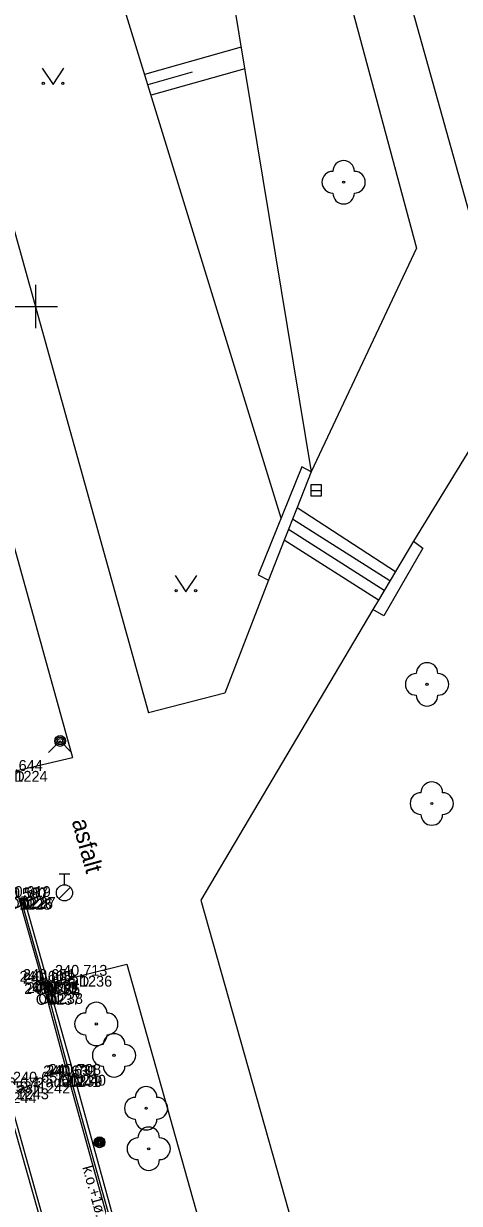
# Model space of a CAD drawing. Extents: x -599098 to -598820, y -1159597 to -1158744.
# Drawn here: x -598950.6 to -598930.4, y -1159141.4 to -1159086.9 of the extents above; entities that cross this region are included whole.
import ezdxf

# ---------------------------------------------------------------- set-up
doc = ezdxf.new("R2010")
doc.units = 0
for name, color, linetype in [('body', 7, 'Continuous'), ('druh pozemku stromy', 7, 'Continuous'), ('hektometrická síť', 7, 'Continuous'), ('kresba', 7, 'Continuous'), ('kódy bodů', 7, 'Continuous'), ('popisy', 7, 'Continuous'), ('vodorovné dopravní značení_bílé', 7, 'Continuous'), ('výšky bodů', 7, 'Continuous'), ('značky IS', 7, 'Continuous'), ('čísla bodů', 7, 'Continuous')]:
    doc.layers.add(name, color=color, linetype=linetype)

msp = doc.modelspace()

# ---------------------------------------------------------------- linework, layer by layer
at = {"layer": 'body'}
for p, q in [((-598949.602, -1159131.15), (-598949.602, -1159131.15)), ((-598949.491, -1159131.071), (-598949.491, -1159131.071)), ((-598949.444, -1159131.241), (-598949.444, -1159131.241)), ((-598947.965, -1159130.878), (-598947.965, -1159130.878)), ((-598949.433, -1159131.716), (-598949.433, -1159131.716)), ((-598949.315, -1159131.673), (-598949.315, -1159131.673)), ((-598948.51, -1159135.517), (-598948.51, -1159135.517)), ((-598948.421, -1159135.492), (-598948.421, -1159135.492)), ((-598948.253, -1159135.448), (-598948.253, -1159135.448)), ((-598949.904, -1159135.807), (-598949.904, -1159135.807))]:
    msp.add_line(p, q, dxfattribs=at)
at = {"layer": 'druh pozemku stromy'}
for points in [[(-598949.706, -1159088.996), (-598949.206, -1159089.746), (-598948.706, -1159088.996)], [(-598943.574, -1159112.407), (-598943.074, -1159113.157), (-598942.574, -1159112.407)]]:
    msp.add_lwpolyline(points, dxfattribs=at)
for centre in [(-598949.656, -1159089.695), (-598948.757, -1159089.695), (-598935.79, -1159094.26), (-598943.524, -1159113.107), (-598942.624, -1159113.107), (-598931.94, -1159117.43), (-598931.72, -1159122.93), (-598947.21, -1159133.1), (-598946.39, -1159134.55), (-598944.91, -1159136.99), (-598944.79, -1159138.86)]:
    msp.add_circle(centre, 0.05, dxfattribs=at)
for centre, start, end in [((-598935.79, -1159093.76), 0, 180), ((-598936.29, -1159094.26), 90, 270), ((-598935.29, -1159094.26), 270, 90), ((-598935.79, -1159094.76), 180, 0), ((-598931.94, -1159116.93), 0, 180), ((-598932.44, -1159117.43), 90, 270), ((-598931.44, -1159117.43), 270, 90), ((-598931.94, -1159117.93), 180, 0), ((-598931.72, -1159122.43), 0, 180), ((-598932.22, -1159122.93), 90, 270), ((-598931.22, -1159122.93), 270, 90), ((-598931.72, -1159123.43), 180, 0), ((-598947.21, -1159132.6), 0, 180), ((-598947.71, -1159133.1), 90, 270), ((-598946.71, -1159133.1), 270, 90), ((-598947.21, -1159133.6), 180, 0), ((-598946.39, -1159134.05), 0, 180), ((-598946.89, -1159134.55), 90, 270), ((-598945.89, -1159134.55), 270, 90), ((-598946.39, -1159135.05), 180, 0), ((-598944.91, -1159136.49), 0, 180), ((-598945.41, -1159136.99), 90, 270), ((-598944.41, -1159136.99), 270, 90), ((-598944.91, -1159137.49), 180, 0), ((-598944.79, -1159138.36), 0, 180), ((-598945.29, -1159138.86), 90, 270), ((-598944.29, -1159138.86), 270, 90), ((-598944.79, -1159139.36), 180, 0)]:
    msp.add_arc(centre, 0.5, start, end, dxfattribs=at)
at = {"layer": 'hektometrická síť'}
for p, q in [((-598950, -1159101), (-598950, -1159099)), ((-598951, -1159100), (-598949, -1159100))]:
    msp.add_line(p, q, dxfattribs=at)
at = {"layer": 'kresba'}
for p, q in [((-598944.816, -1159061.959), (-598937.29, -1159107.63)), ((-598959.455, -1159066.177), (-598944.8, -1159118.74)), ((-598963.201, -1159067.235), (-598948.308, -1159120.805)), ((-598940.519, -1159088.034), (-598944.978, -1159089.287)), ((-598942.79, -1159089.188), (-598944.83, -1159089.766)), ((-598940.356, -1159089.027), (-598944.684, -1159090.24)), ((-598937.29, -1159107.63), (-598937.94, -1159109.27)), ((-598937.94, -1159109.27), (-598938.53, -1159110.77)), ((-598937.94, -1159109.27), (-598933.4, -1159112.23)), ((-598933.66, -1159112.66), (-598938.15, -1159109.8)), ((-598933.92, -1159113.1), (-598938.34, -1159110.29)), ((-598938.53, -1159110.77), (-598939.26, -1159112.63)), ((-598934.18, -1159113.54), (-598938.53, -1159110.77)), ((-598934.18, -1159113.54), (-598934.45, -1159113.98)), ((-598934.45, -1159113.98), (-598942.39, -1159127.39)), ((-598950.946, -1159121.423), (-598948.308, -1159120.805)), ((-598949.675, -1159131.169), (-598950.775, -1159127.328)), ((-598949.602, -1159131.15), (-598950.699, -1159127.295)), ((-598950.577, -1159127.242), (-598949.491, -1159131.071)), ((-598947.965, -1159130.878), (-598945.794, -1159130.345)), ((-598945.794, -1159130.345), (-598936.061, -1159164.919)), ((-598948.51, -1159135.517), (-598949.675, -1159131.169)), ((-598949.433, -1159131.716), (-598949.602, -1159131.15)), ((-598949.491, -1159131.071), (-598949.444, -1159131.241)), ((-598949.444, -1159131.241), (-598947.965, -1159130.878)), ((-598949.444, -1159131.241), (-598949.315, -1159131.673)), ((-598948.421, -1159135.492), (-598949.433, -1159131.716)), ((-598949.315, -1159131.673), (-598948.253, -1159135.448)), ((-598945.376, -1159146.794), (-598948.51, -1159135.517)), ((-598945.272, -1159146.749), (-598948.421, -1159135.492)), ((-598948.253, -1159135.448), (-598945.146, -1159146.717)), ((-598951.457, -1159136.252), (-598948.302, -1159147.441))]:
    msp.add_line(p, q, dxfattribs=at)
for points in [[(-598940.18, -1159040.43), (-598942.4, -1159041.16), (-598944.28, -1159043.88), (-598939.55, -1159061.52), (-598929.18, -1159098.6)], [(-598947.19, -1159042.65), (-598943.18, -1159057.36), (-598932.43, -1159097.3), (-598937.29, -1159107.63)], [(-598938.67, -1159109.76), (-598949.024, -1159076.155), (-598952.81, -1159064.352)], [(-598928.37, -1159105.76), (-598929.62, -1159106.03), (-598932.56, -1159110.82)], [(-598937.29, -1159107.63), (-598937.72, -1159107.39), (-598939.73, -1159112.38), (-598939.26, -1159112.63)], [(-598932.56, -1159110.82), (-598932.13, -1159111.14), (-598933.94, -1159114.27), (-598934.45, -1159113.98)], [(-598932.56, -1159110.82), (-598933.4, -1159112.23), (-598934.18, -1159113.54)], [(-598939.26, -1159112.63), (-598941.27, -1159117.83), (-598944.8, -1159118.74)], [(-598942.39, -1159127.39), (-598932.11, -1159163.78)]]:
    msp.add_lwpolyline(points, dxfattribs=at)
at = {"layer": 'vodorovné dopravní značení_bílé'}
msp.add_lwpolyline([(-599004.61, -1158945.262), (-599003.444, -1158949.453), (-598994.165, -1158982.574), (-598991.03, -1158993.767), (-598984.936, -1159015.967), (-598978.352, -1159039.475), (-598975.241, -1159050.571), (-598972.159, -1159061.595), (-598965.954, -1159083.858), (-598959.703, -1159106.35), (-598956.549, -1159117.387), (-598953.462, -1159128.573), (-598948.06, -1159147.837), (-598944.998, -1159159.054), (-598943.117, -1159165.778)], dxfattribs=at)
at = {"layer": 'značky IS'}
for p, q in [((-598937.31, -1159108.48), (-598936.81, -1159108.48)), ((-598948.93, -1159126.175), (-598948.43, -1159126.175)), ((-598948.68, -1159126.675), (-598948.68, -1159126.175)), ((-598948.938, -1159127.322), (-598948.408, -1159126.792))]:
    msp.add_line(p, q, dxfattribs=at)
msp.add_lwpolyline([(-598937.31, -1159108.73), (-598936.81, -1159108.73), (-598936.81, -1159108.23), (-598937.31, -1159108.23)], close=True, dxfattribs=at)
msp.add_lwpolyline([(-598949.41, -1159120.57), (-598948.88, -1159120.04), (-598948.35, -1159120.57)], dxfattribs=at)
for centre, radius in [((-598948.88, -1159120.04), 0.25), ((-598948.88, -1159120.04), 0.18), ((-598948.88, -1159120.04), 0.11), ((-598948.68, -1159127.05), 0.375), ((-598947.06, -1159138.56), 0.25), ((-598947.06, -1159138.56), 0.2), ((-598947.06, -1159138.56), 0.15), ((-598947.06, -1159138.56), 0.1), ((-598947.06, -1159138.56), 0.05)]:
    msp.add_circle(centre, radius, dxfattribs=at)

# ---------------------------------------------------------------- texts
at = {"layer": 'kódy bodů'}
for s, p in [('OD', (-598951.518, -1159121.923)), ('OD', (-598951.271, -1159127.795)), ('ON', (-598951.147, -1159127.742)), ('OD', (-598950.174, -1159131.65)), ('ON', (-598950.061, -1159131.571)), ('ON', (-598950.014, -1159131.741)), ('OD', (-598948.537, -1159131.378)), ('OD', (-598950.005, -1159132.216)), ('ON', (-598949.885, -1159132.173)), ('1rade', (-598950.15, -1159136.017)), ('OD', (-598948.993, -1159135.992)), ('ON', (-598948.823, -1159135.948)), ('asf', (-598950.837, -1159136.307))]:
    msp.add_text(s, height=0.5, dxfattribs=at).set_placement(p)
at = {"layer": 'popisy'}
for s, height, rotation, p in [('asfalt', 0.8, 285.5601, (-598948.351, -1159123.742)), ('k.o.+1ø.', 0.5, 285.5312, (-598947.862, -1159139.715))]:
    msp.add_text(s, height=height, rotation=rotation, dxfattribs=at).set_placement(p)
at = {"layer": 'výšky bodů'}
for s, p in [('240.644', (-598952.098, -1159121.423)), ('240.590', (-598951.941, -1159127.328)), ('240.587', (-598951.851, -1159127.295)), ('240.619', (-598951.729, -1159127.242)), ('240.605', (-598950.754, -1159131.15)), ('240.651', (-598950.599, -1159131.071)), ('240.713', (-598949.117, -1159130.878)), ('240.668', (-598950.596, -1159131.241)), ('240.611', (-598950.541, -1159131.716)), ('240.691', (-598950.423, -1159131.673)), ('240.639', (-598949.662, -1159135.517)), ('240.631', (-598949.529, -1159135.492)), ('240.708', (-598949.405, -1159135.448)), ('240.672', (-598952.039, -1159136.074)), ('240.657', (-598951.056, -1159135.807)), ('240.653', (-598952.609, -1159136.252))]:
    msp.add_text(s, height=0.5, dxfattribs=at).set_placement(p)
at = {"layer": 'čísla bodů'}
for s, p in [('1224', (-598950.946, -1159121.923)), ('1228', (-598950.775, -1159127.828)), ('1226', (-598950.699, -1159127.795)), ('1227', (-598950.577, -1159127.742)), ('1233', (-598949.602, -1159131.65)), ('1234', (-598949.491, -1159131.571)), ('1235', (-598949.444, -1159131.741)), ('1236', (-598947.965, -1159131.378)), ('1237', (-598949.433, -1159132.216)), ('1238', (-598949.315, -1159132.173)), ('1241', (-598948.51, -1159136.017)), ('1239', (-598948.421, -1159135.992)), ('1240', (-598948.253, -1159135.948)), ('1243', (-598950.887, -1159136.574)), ('1242', (-598949.904, -1159136.307)), ('1244', (-598951.457, -1159136.752))]:
    msp.add_text(s, height=0.5, dxfattribs=at).set_placement(p)

doc.saveas('drawing.dxf')
